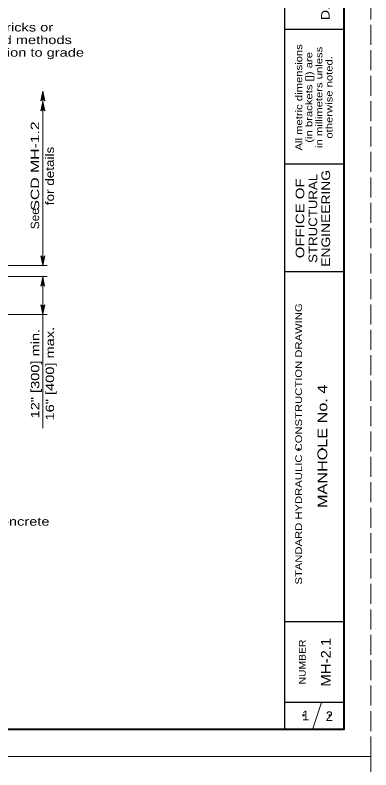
# Model space of a CAD drawing. Extents: x 1170.6 to 1204.6, y 975 to 1019.
# Drawn here: x 1197.98 to 1204.59, y 996.78 to 1010.8 of the extents above; entities that cross this region are included whole.
import ezdxf
from ezdxf.enums import TextEntityAlignment as Align

# ---------------------------------------------------------------- set-up
doc = ezdxf.new("R2010")
doc.units = 0
doc.header["$LTSCALE"] = 0.062
doc.header["$PDMODE"] = 32
doc.header["$PDSIZE"] = 0.031
doc.linetypes.add('LONG_DASHED', pattern=[7.5, 6, -1.5])
doc.layers.add('1', color=7, linetype='Continuous', lineweight=13)

msp = doc.modelspace()

# ---------------------------------------------------------------- linework, layer by layer
at = {"layer": '1', "lineweight": 25}
for p, q in [((1202.99275, 997.52625), (1202.99275, 1018.52625)), ((1204.09275, 1018.52625), (1204.09275, 997.52625)), ((1204.09275, 1010.52625), (1202.99275, 1010.52625)), ((1204.09275, 1008.02625), (1202.99275, 1008.02625)), ((1204.09275, 1006.02625), (1202.99275, 1006.02625)), ((1204.09275, 999.52625), (1202.99275, 999.52625)), ((1204.09275, 998.02625), (1202.99275, 998.02625))]:
    msp.add_line(p, q, dxfattribs=at)
at = {"layer": '1'}
for p, q in [((1198.47358, 1009.22117), (1198.49842, 1009.38333)), ((1198.484, 1009.22733), (1198.49842, 1009.38333)), ((1198.49842, 1006.14658), (1198.49842, 1009.38333)), ((1198.49842, 1009.23017), (1198.49842, 1009.38333)), ((1198.50975, 1009.2285), (1198.49842, 1009.38333)), ((1198.52083, 1009.22308), (1198.49842, 1009.38333)), ((1198.47367, 1009.02992), (1198.49842, 1009.192)), ((1198.484, 1009.036), (1198.49842, 1009.192)), ((1198.49842, 1009.03883), (1198.49842, 1009.192)), ((1198.50975, 1009.03717), (1198.49842, 1009.192)), ((1198.52083, 1009.03175), (1198.49842, 1009.192)), ((1198.476, 1006.30683), (1198.49842, 1006.14658)), ((1198.48708, 1006.30142), (1198.49842, 1006.14658)), ((1198.52317, 1006.30875), (1198.49842, 1006.14658)), ((1198.51275, 1006.30258), (1198.49842, 1006.14658)), ((1198.49842, 1006.29975), (1198.49842, 1006.14658)), ((1194.847, 1006.14658), (1198.57708, 1006.14658)), ((1194.75317, 1005.93808), (1198.57708, 1005.93808)), ((1198.4705, 1005.77458), (1198.49525, 1005.93675)), ((1198.48083, 1005.78075), (1198.49525, 1005.93675)), ((1198.49525, 1005.78358), (1198.49525, 1005.93675)), ((1198.50658, 1005.78192), (1198.49525, 1005.93675)), ((1198.51767, 1005.7765), (1198.49525, 1005.93675)), ((1198.49842, 1003.12508), (1198.49842, 1005.93858)), ((1198.476, 1005.4005), (1198.49842, 1005.24033)), ((1198.48708, 1005.39508), (1198.49842, 1005.24033)), ((1198.52317, 1005.40242), (1198.49842, 1005.24033)), ((1198.51275, 1005.39633), (1198.49842, 1005.24033)), ((1198.49842, 1005.3935), (1198.49842, 1005.24033)), ((1194.75117, 1005.23642), (1198.57708, 1005.23642)), ((1203.50942, 997.52625), (1203.67608, 998.02625))]:
    msp.add_line(p, q, dxfattribs=at)
at = {"layer": '1', "linetype": 'LONG_DASHED'}
for points in [[(1170.59275, 997.02625), (1204.59275, 997.02625), (1204.59275, 1019.02625), (1170.59275, 1019.02625)], [(1170.59275, 975.02625), (1204.59275, 975.02625), (1204.59275, 997.02625), (1170.59275, 997.02625)]]:
    msp.add_lwpolyline(points, close=True, dxfattribs=at)
at = {"layer": '1', "lineweight": 25}
msp.add_lwpolyline([(1204.09275, 997.52625), (1172.59275, 997.52625), (1172.59275, 1018.52625)], dxfattribs=at)
at = {"layer": '1', "lineweight": 40}
msp.add_lwpolyline([(1172.59275, 1018.52625), (1204.09275, 1018.52625), (1204.09275, 997.52625), (1172.59275, 997.52625)], close=True, dxfattribs=at)
at = {"layer": '1'}
for points in [[(1198.463, 1009.20633), (1198.49842, 1009.38333), (1198.53375, 1009.20633)], [(1198.463, 1009.015), (1198.49842, 1009.192), (1198.53383, 1009.015)], [(1198.53375, 1006.32358), (1198.49842, 1006.14658), (1198.463, 1006.32358)], [(1198.45983, 1005.75975), (1198.49525, 1005.93675), (1198.53067, 1005.75975)], [(1198.53375, 1005.41733), (1198.49842, 1005.24033), (1198.463, 1005.41733)]]:
    msp.add_lwpolyline(points, dxfattribs=at)
for centre, start, end in [((1198.49842, 1009.19202), 22.08782, 157.91395), ((1198.49846, 1009.00073), 22.08782, 157.91395), ((1198.49835, 1006.33789), 202.08782, 337.91395), ((1198.49528, 1005.74542), 22.08782, 157.91395), ((1198.49835, 1005.43159), 202.08782, 337.91395)]:
    msp.add_arc(centre, 0.0382, start, end, dxfattribs=at)
for p in [(1203.25017, 1002.73225), (1203.683, 1002.73958), (1203.34083, 997.79), (1203.82925, 997.789)]:
    msp.add_point(p, dxfattribs=at)

# ---------------------------------------------------------------- texts
for s, height, width, p in [('D. Gruver', 0.16, 1.25, (1203.82617, 1011.28042)), ('All metric dimensions', 0.125, 1.25, (1203.31658, 1009.26833)), ('in millimeters unless', 0.125, 1.25, (1203.69158, 1009.26837)), ('(in brackets []) are', 0.125, 1.25, (1203.50408, 1009.26833)), ('otherwise noted.', 0.125, 1.25, (1203.87908, 1009.26833)), ('    SCD MH-1.2', 0.156, 1.4, (1198.42917, 1007.83129)), ('for details', 0.156, 1.2, (1198.704, 1007.80758)), ('ENGINEERING', 0.16, 1.2, (1203.8345, 1007.02079)), ('STRUCTURAL', 0.16, 1.15, (1203.5945, 1007.02071)), ('OFFICE OF', 0.16, 1.3, (1203.3545, 1007.02071)), ('See', 0.156, 1.05, (1198.42867, 1007.01471)), ('STANDARD HYDRAULIC CONSTRUCTION DRAWING', 0.125, 1.25, (1203.31267, 1002.83029)), ('16" [400] max.', 0.156, 1.3, (1198.70675, 1004.13642)), ('12" [300] min.', 0.156, 1.3, (1198.43275, 1004.13646)), ('MANHOLE No. 4', 0.18, 1.25, (1203.78058, 1002.78638)), ('MH-2.1', 0.18, 1.15, (1203.84625, 998.77662)), ('NUMBER', 0.125, 1.15, (1203.37975, 998.78033))]:
    msp.add_text(s, height=height, rotation=90, dxfattribs=dict(at, width=width)).set_placement(p, align=Align.CENTER)
at = {"layer": '1', "width": 1.3}
for s, p in [('Grade rings, bricks or', (1196.09692, 1010.49158)), ('other approved methods', (1196.09692, 1010.25758)), ('for reconstruction to grade ', (1196.09692, 1010.02358)), ('Class C concrete', (1196.55692, 1001.313))]:
    msp.add_text(s, height=0.156, dxfattribs=at).set_placement(p)
at = {"layer": '1'}
for s, p in [('1', (1203.3806, 997.69633)), ('2', (1203.82004, 997.68375))]:
    msp.add_text(s, height=0.18, dxfattribs=at).set_placement(p, align=Align.CENTER)

doc.saveas('drawing.dxf')
